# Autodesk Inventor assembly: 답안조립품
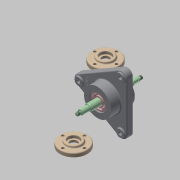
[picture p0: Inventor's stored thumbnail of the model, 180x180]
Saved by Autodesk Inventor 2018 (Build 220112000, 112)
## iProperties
Created: 2023-04
Part Number: 답안조립품
Material: 일반
Document SubType Name: Assembly
Designer: home
Author: home
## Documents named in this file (5)
- C:\Users\home\Desktop\730407V1004\답안조립품.iam
- C:\Users\home\Desktop\730407V1004\본체.ipt
- C:\Users\home\Desktop\730407V1004\베어링 6204.ipt
- C:\Users\home\Desktop\730407V1004\축.ipt
- C:\Users\home\Desktop\730407V1004\커버.ipt
